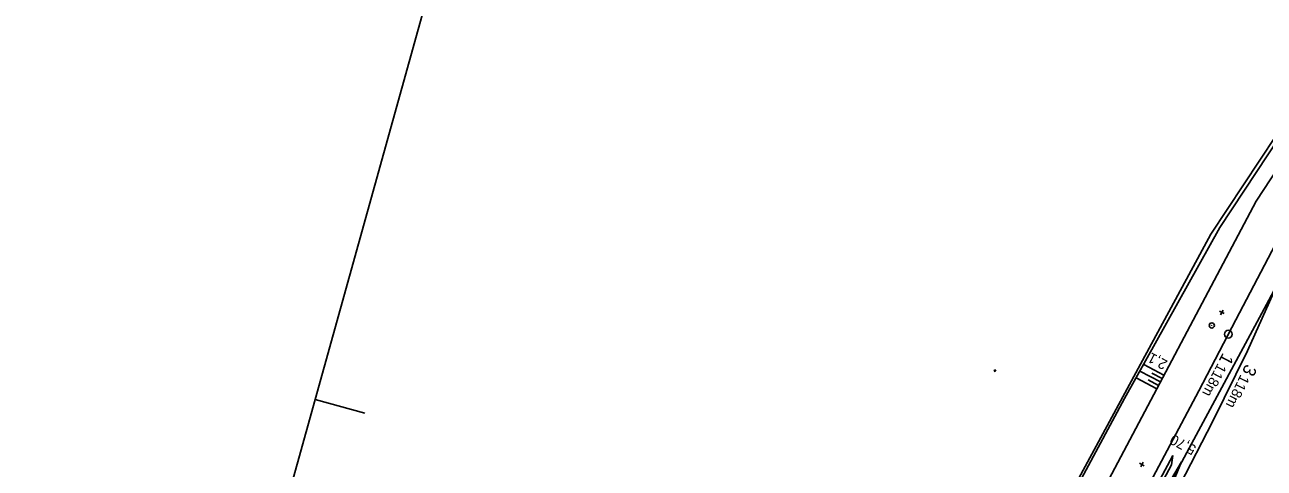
# Model space of a CAD drawing. Extents: x -795094 to -794639, y -1135368 to -1134681.
# Drawn here: x -795037.8 to -794797.7, y -1134896.9 to -1134811 of the extents above; entities that cross this region are included whole.
import ezdxf

# ---------------------------------------------------------------- set-up
doc = ezdxf.new("R2010")
doc.units = 0
for name, color, linetype in [('0381KM005-009P - Vrstva 1', 7, 'Continuous'), ('0381KM005-009P - Vrstva 48', 7, 'Continuous'), ('0381KM005-009P - Vrstva 49', 7, 'Continuous'), ('0381KM005-009P - Vrstva 7', 7, 'Continuous'), ('formát', 7, 'Continuous'), ('hran DP - hran DP', 7, 'Continuous'), ('vyt_sit - polygon', 7, 'Continuous')]:
    doc.layers.add(name, color=color, linetype=linetype)

msp = doc.modelspace()

# ---------------------------------------------------------------- linework, layer by layer
at = {"layer": '0381KM005-009P - Vrstva 1'}
for points in [[(-794788.58, -1134840.28), (-794803.19, -1134868.16), (-794810.38, -1134881.86), (-794818.66, -1134897.6), (-794826.62, -1134912.5), (-794834.33, -1134926.85), (-794861.92, -1134977.99)], [(-794786.96, -1134841.36), (-794793.84, -1134858.32), (-794800.91, -1134874.12), (-794807.73, -1134887.87), (-794826.52, -1134924.29), (-794833.34, -1134937.13), (-794839.37, -1134947.86), (-794840.75, -1134950.16), (-794846.08, -1134958.61), (-794850.88, -1134965.55), (-794860.1, -1134978.74)]]:
    msp.add_lwpolyline(points, dxfattribs=at)
at = {"layer": '0381KM005-009P - Vrstva 48'}
for p, q in [((-794817.11, -1134878.83), (-794821.04, -1134876.75)), ((-794818.52, -1134881.48), (-794822.5, -1134879.37)), ((-794817.81, -1134880.16), (-794821.77, -1134878.06)), ((-794818.17, -1134880.82), (-794820.15, -1134879.77)), ((-794817.46, -1134879.49), (-794819.43, -1134878.45))]:
    msp.add_line(p, q, dxfattribs=at)
at = {"layer": '0381KM005-009P - Vrstva 49'}
for p, q in [((-794781.56, -1134812.71), (-794806.26, -1134850.22)), ((-794779.34, -1134814.68), (-794799.26, -1134845.15)), ((-794799.26, -1134845.15), (-794840.65, -1134923.24)), ((-794806.26, -1134850.22), (-794824.73, -1134883.39)), ((-794849.62, -1134877.9), (-794850.1, -1134878.05)), ((-794849.94, -1134877.74), (-794849.79, -1134878.21)), ((-794824.73, -1134883.39), (-794837.68, -1134907.33))]:
    msp.add_line(p, q, dxfattribs=at)
for points in [[(-794815.37, -1134894.44), (-794815.67, -1134896.21), (-794830.44, -1134923.9), (-794846.52, -1134953.51), (-794848.28, -1134955.61)], [(-794815.37, -1134894.44), (-794830.99, -1134923.68), (-794848.28, -1134955.61)], [(-794813.73, -1134895.61), (-794815.7, -1134900.49), (-794822, -1134912.52), (-794829.49, -1134927.01), (-794835.62, -1134938.73), (-794838.1, -1134942.66)], [(-794813.73, -1134895.61), (-794816.27, -1134900.06), (-794822.55, -1134912.27), (-794829.83, -1134926.6), (-794836.24, -1134938.45), (-794838.1, -1134942.66)]]:
    msp.add_lwpolyline(points, dxfattribs=at)
at = {"layer": '0381KM005-009P - Vrstva 7'}
for p, q in [((-794805.45, -1134866.91), (-794806.34, -1134866.45)), ((-794805.66, -1134866.24), (-794806.13, -1134867.13)), ((-794807.82, -1134869.17), (-794807.87, -1134869.26)), ((-794821.83, -1134895.92), (-794820.94, -1134896.39)), ((-794821.62, -1134896.6), (-794821.15, -1134895.71))]:
    msp.add_line(p, q, dxfattribs=at)
for centre, radius in [((-794807.84, -1134869.22), 0.5), ((-794804.63, -1134870.91), 0.75)]:
    msp.add_circle(centre, radius, dxfattribs=at)
at = {"layer": 'formát'}
for p, q in [((-794925.31, -1134681.22), (-794981.56, -1134883.54)), ((-794981.56, -1134883.54), (-795037.81, -1135085.87)), ((-794981.56, -1134883.54), (-794971.92, -1134886.22))]:
    msp.add_line(p, q, dxfattribs=at)
at = {"layer": 'hran DP - hran DP'}
for p, q in [((-794808.02, -1134851.51), (-794775.44, -1134802.2)), ((-794834.03, -1134899.62), (-794808.02, -1134851.51))]:
    msp.add_line(p, q, dxfattribs=at)
at = {"layer": 'vyt_sit - polygon'}
msp.add_line((-794869.14, -1134998.77), (-794781.23, -1134835.33), dxfattribs=at)

# ---------------------------------------------------------------- texts
at = {"layer": '0381KM005-009P - Vrstva 1'}
for s, height, rotation, p in [('1', 2.5, 242.3222, (-794805.68, -1134874.39)), ('118m', 2, 242.2272, (-794806.66, -1134876.42)), ('3', 2.5, 243.6203, (-794801.22, -1134876.56)), ('118m', 2, 243.6203, (-794802.23, -1134878.61)), ('5,70', 2, 152.2272, (-794810.68, -1134892.67))]:
    msp.add_text(s, height=height, rotation=rotation, dxfattribs=at).set_placement(p)
at = {"layer": '0381KM005-009P - Vrstva 48'}
msp.add_text('2,1', height=2, rotation=152.0771, dxfattribs=at).set_placement((-794816.27, -1134876.14))

doc.saveas('drawing.dxf')
